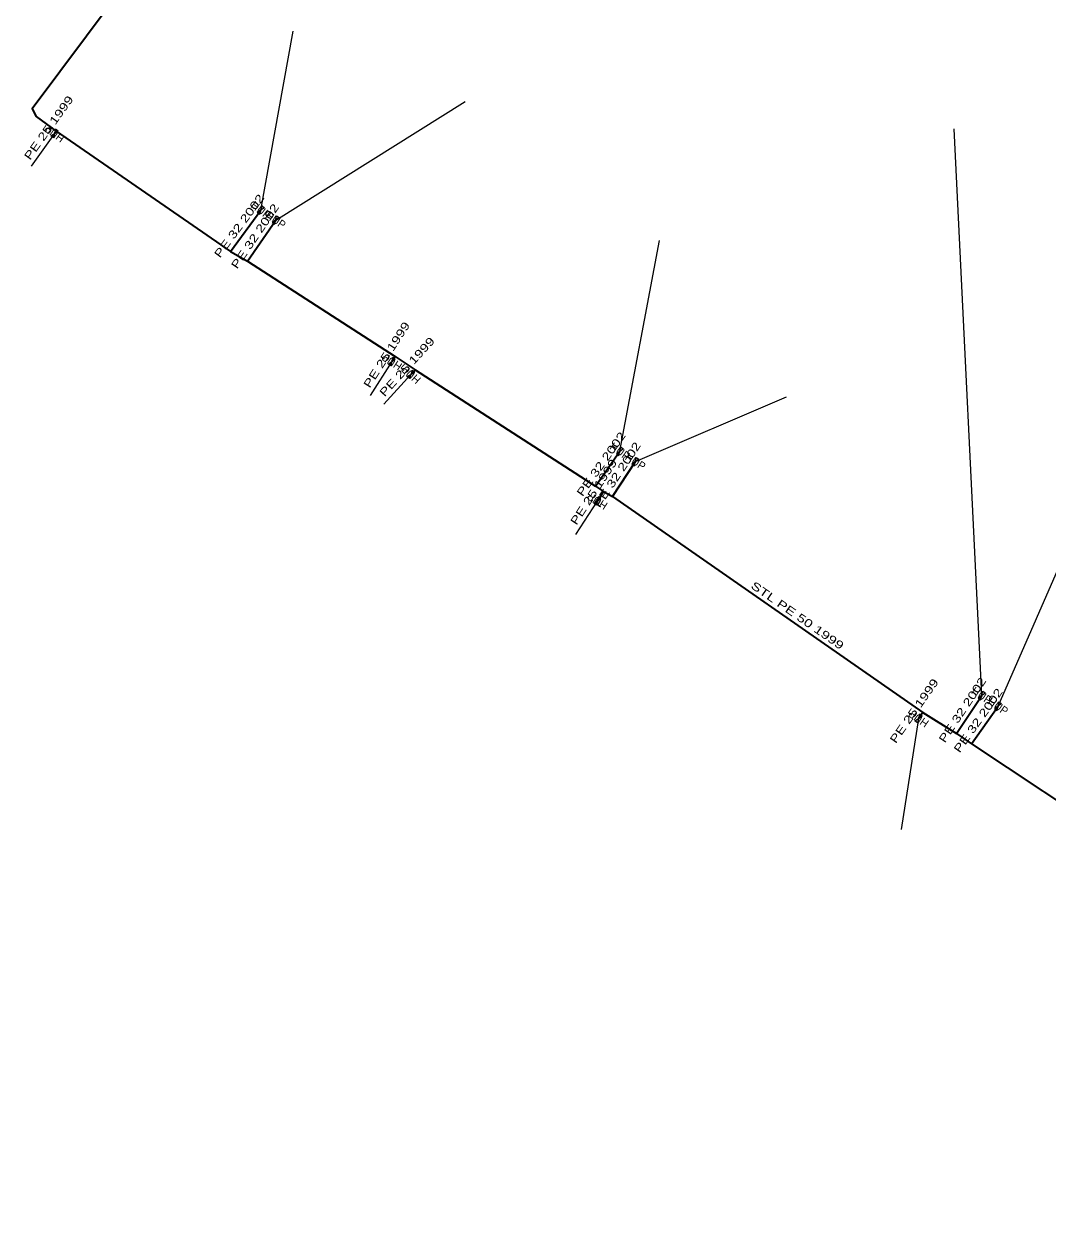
# Model space of a CAD drawing. Extents: x -737484 to -734496, y -1033882 to -1030666.
# Drawn here: x -736486.5 to -736358.7, y -1032729.9 to -1032578.8 of the extents above; entities that cross this region are included whole.
import ezdxf
from ezdxf.enums import TextEntityAlignment as Align

# ---------------------------------------------------------------- set-up
doc = ezdxf.new("R2010")
doc.units = 0
doc.header["$LTSCALE"] = 0.4
for name, color, linetype, lineweight in [('1', 7, 'Continuous', 13), ('22', 7, 'Continuous', 25), ('5', 7, 'Continuous', 35), ('7', 7, 'Continuous', 35)]:
    doc.layers.add(name, color=color, linetype=linetype, lineweight=lineweight)
doc.layers.add('2', color=7, linetype='Continuous')

msp = doc.modelspace()

# ---------------------------------------------------------------- linework, layer by layer
at = {"layer": '1'}
for points in [[(-736482.9, -1032592.949), (-736483.223, -1032592.713), (-736482.312, -1032592.14), (-736482.635, -1032591.904)], [(-736456.838, -1032601.47), (-736456.519, -1032601.711), (-736457.44, -1032602.268), (-736457.121, -1032602.509)], [(-736455.025, -1032602.712), (-736454.693, -1032602.936), (-736455.584, -1032603.541), (-736455.252, -1032603.765)], [(-736440.742, -1032621.455), (-736441.078, -1032621.237), (-736440.197, -1032620.616), (-736440.533, -1032620.398)], [(-736438.443, -1032623.034), (-736438.741, -1032622.766), (-736437.774, -1032622.291), (-736438.072, -1032622.023)], [(-736412.017, -1032631.605), (-736411.689, -1032631.835), (-736412.59, -1032632.424), (-736412.262, -1032632.654)], [(-736410.105, -1032632.89), (-736409.769, -1032633.108), (-736410.65, -1032633.729), (-736410.314, -1032633.947)], [(-736415.073, -1032638.865), (-736415.409, -1032638.647), (-736414.528, -1032638.026), (-736414.864, -1032637.808)], [(-736366.836, -1032662.102), (-736366.504, -1032662.326), (-736367.395, -1032662.931), (-736367.063, -1032663.155)], [(-736364.797, -1032663.444), (-736364.469, -1032663.674), (-736365.37, -1032664.263), (-736365.042, -1032664.493)], [(-736374.971, -1032666.033), (-736375.299, -1032665.803), (-736374.398, -1032665.214), (-736374.726, -1032664.984)]]:
    msp.add_lwpolyline(points, close=True, dxfattribs=at)
at = {"layer": '22'}
for p, q in [((-736456.98, -1032601.99), (-736452.974, -1032579.652)), ((-736455.139, -1032603.239), (-736431.469, -1032588.429)), ((-736482.768, -1032592.427), (-736485.676, -1032596.495)), ((-736366.95, -1032662.629), (-736370.387, -1032591.84)), ((-736412.14, -1032632.13), (-736407.189, -1032605.788)), ((-736364.92, -1032663.969), (-736340.804, -1032608.744)), ((-736440.638, -1032620.927), (-736443.335, -1032625.137)), ((-736438.258, -1032622.529), (-736441.627, -1032626.223)), ((-736410.21, -1032633.419), (-736391.323, -1032625.316)), ((-736414.969, -1032638.337), (-736417.688, -1032642.533)), ((-736374.849, -1032665.509), (-736377.028, -1032679.38))]:
    msp.add_line(p, q, dxfattribs=at)
at = {"layer": '5'}
msp.add_lwpolyline([(-736477.985, -1032573.565), (-736475.29, -1032575.61), (-736485.57, -1032589.34), (-736485.04, -1032590.3), (-736482.57, -1032592.15), (-736460.8, -1032607.15), (-736458.64, -1032608.39), (-736440.23, -1032620.29), (-736437.73, -1032621.95), (-736415.21, -1032636.47), (-736414.2, -1032637.15), (-736413.09, -1032637.79), (-736374.31, -1032664.74), (-736370.11, -1032667.36), (-736368.25, -1032668.68), (-736350.272, -1032680.583), (-736343.55, -1032685), (-736325.04, -1032697.15), (-736315.65, -1032703.23), (-736278.9, -1032729.88)], dxfattribs=at)
at = {"layer": '7'}
for p, q in [((-736482.57, -1032592.15), (-736482.768, -1032592.427)), ((-736460.8, -1032607.15), (-736456.98, -1032601.99)), ((-736458.64, -1032608.39), (-736455.139, -1032603.239)), ((-736440.23, -1032620.29), (-736440.638, -1032620.927)), ((-736437.73, -1032621.95), (-736438.258, -1032622.529)), ((-736415.21, -1032636.47), (-736412.14, -1032632.13)), ((-736413.09, -1032637.79), (-736410.21, -1032633.419)), ((-736414.2, -1032637.15), (-736414.969, -1032638.337)), ((-736370.11, -1032667.36), (-736366.95, -1032662.629)), ((-736374.31, -1032664.74), (-736374.849, -1032665.509)), ((-736368.25, -1032668.68), (-736364.92, -1032663.969))]:
    msp.add_line(p, q, dxfattribs=at)

# ---------------------------------------------------------------- texts
at = {"layer": '2', "width": 0.95}
for rotation, p in [(144, (-736482.4736, -1032592.022)), (323, (-736457.2804, -1032602.3885)), (326, (-736455.4181, -1032603.6529)), (147, (-736440.3652, -1032620.5071)), (138, (-736437.9229, -1032622.1573)), (325, (-736412.4263, -1032632.5389)), (327, (-736410.4818, -1032633.8379)), (147, (-736414.6962, -1032637.9171)), (326, (-736367.2291, -1032663.0429)), (325, (-736365.2063, -1032664.3779)), (145, (-736374.5617, -1032665.0991))]:
    msp.add_text('HUP', height=1, rotation=rotation, dxfattribs=at).set_placement(p, align=Align.CENTER)
at = {"layer": '5', "width": 1.4}
msp.add_text('STL PE 50 1999', height=1, rotation=325.203, dxfattribs=at).set_placement((-736390.2538, -1032653.05), align=Align.CENTER)
at = {"layer": '7', "width": 1.35}
for s, rotation, p in [('PE 25 1999', 54.443, (-736483.0756, -1032591.9973)), ('PE 32 2002', 53.487, (-736459.2916, -1032604.272)), ('PE 32 2002', 55.797, (-736457.3024, -1032605.5331)), ('PE 25 1999', 57.36, (-736440.8548, -1032620.3382)), ('PE 25 1999', 47.638, (-736438.3633, -1032621.9019)), ('PE 32 2002', 54.725, (-736414.0823, -1032634.0107)), ('PE 32 2002', 56.62, (-736412.0666, -1032635.3286)), ('PE 25 1999', 57.063, (-736415.0037, -1032637.4714)), ('PE 25 1999', 54.973, (-736374.9884, -1032664.837)), ('PE 32 2002', 56.26, (-736368.9454, -1032664.7162)), ('PE 32 2002', 54.745, (-736366.9929, -1032666.0351))]:
    msp.add_text(s, height=1, rotation=rotation, dxfattribs=at).set_placement(p, align=Align.CENTER)

doc.saveas('drawing.dxf')
